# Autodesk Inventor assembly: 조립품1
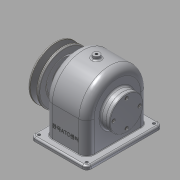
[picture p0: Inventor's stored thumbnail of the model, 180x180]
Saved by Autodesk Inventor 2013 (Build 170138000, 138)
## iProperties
Created: 2016-01
Part Number: 조립품1
Document SubType Name: Assembly
Designer: dgall
Author: dgall
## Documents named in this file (16)
- C:\Users\dgall\Desktop\460105V1014\조립품1.iam
- C:\Users\dgall\Desktop\460105V1014\V-벨트풀리.ipt
- C:\Users\dgall\Desktop\460105V1014\뒤커버.ipt
- C:\Users\dgall\Desktop\460105V1014\멈춤나사 - M4x10.ipt
- C:\Users\dgall\Desktop\460105V1014\베어링 6203.ipt
- C:\Users\dgall\Desktop\460105V1014\볼트 M3 x 8.ipt
- C:\Users\dgall\Desktop\460105V1014\볼트 M3 x 10.ipt
- C:\Users\dgall\Desktop\460105V1014\부시1.ipt
- C:\Users\dgall\Desktop\460105V1014\부시2.ipt
- C:\Users\dgall\Desktop\460105V1014\스퍼기어.ipt
- C:\Users\dgall\Desktop\460105V1014\앞커버.ipt
- C:\Users\dgall\Desktop\460105V1014\오일씰 28 40 8.ipt
- C:\Users\dgall\Desktop\460105V1014\축.ipt
- C:\Users\dgall\Desktop\460105V1014\키 - 5 x 5 x 18.ipt
- C:\Users\dgall\Desktop\460105V1014\키 - 6 x 6 x 22.ipt
- C:\Users\dgall\Desktop\본체1.ipt
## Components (9 placed, 3 different names)
1. V-벨트풀리:1
2. ISO 4762 M3 x 8:1
3. ISO 4762 M3 x 8:2
4. ISO 4762 M3 x 8:3
5. ISO 4762 M3 x 8:4
6. ISO 4762 M3 x 10:1
7. ISO 4762 M3 x 10:2
8. ISO 4762 M3 x 10:3
9. ISO 4762 M3 x 10:4
